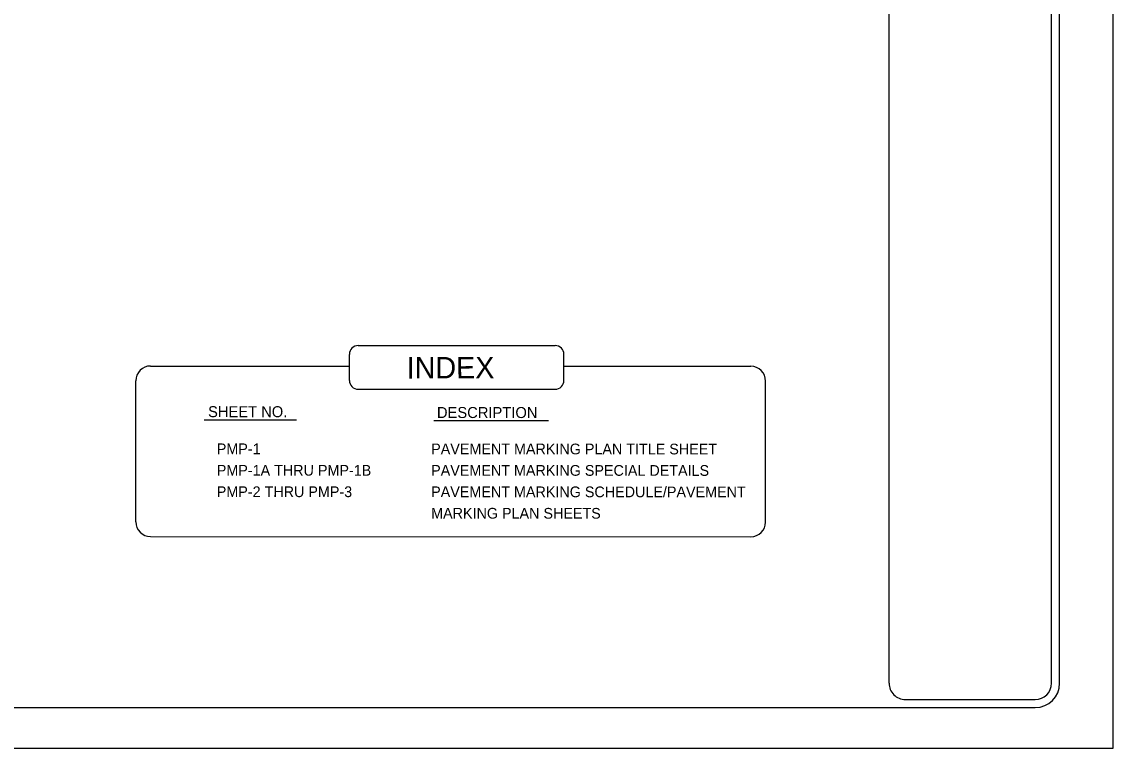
# Model space of a CAD drawing. Extents: x -63 to 3072, y 0 to 1100.
# Drawn here: x 1028 to 1700, y 0 to 447 of the extents above; entities that cross this region are included whole.
import ezdxf

# ---------------------------------------------------------------- set-up
doc = ezdxf.new("R2010")
doc.units = 0
for name, color, linetype in [('Draft_Plan_Labels', 7, 'Continuous'), ('Scratch_Level_0', 7, 'Continuous'), ('Sheet Data Text CELL', 7, 'Continuous'), ('Sheet_RDY_PE_Seal_Cell', 7, 'Continuous')]:
    doc.layers.add(name, color=color, linetype=linetype)

msp = doc.modelspace()

# ---------------------------------------------------------------- linework, layer by layer
at = {"layer": 'Scratch_Level_0'}
for p, q in [((1699.98, 0), (1699.98, 1100)), ((0, 0), (1699.98, 0))]:
    msp.add_line(p, q, dxfattribs=at)
at = {"layer": 'Sheet_RDY_PE_Seal_Cell'}
for p, q in [((1561.97, 39.96), (1562, 1059.93)), ((1662, 39.96), (1662, 1059.91)), ((1667, 39.99), (1667, 1059.91)), ((1229.66, 226.43), (1229.66, 242.45)), ((1361.82, 226.43), (1361.82, 242.45)), ((1107.27, 235.27), (1229.66, 235.22)), ((1361.82, 235.16), (1476.88, 235.1)), ((1098.14, 139.4), (1098.18, 226.19)), ((1485.93, 139.22), (1485.97, 226.01)), ((1140.18, 202.22), (1197.04, 202.19)), ((1281.57, 201.7), (1352.21, 201.67)), ((1107.22, 130.31), (1476.83, 130.14)), ((1571.99, 29.94), (1651.98, 29.94)), ((38.07, 24.99), (1652, 24.99))]:
    msp.add_line(p, q, dxfattribs=at)
for points in [[(1235.11, 247.9), (1356.36, 247.9)], [(1235.11, 220.97), (1356.36, 220.97)]]:
    msp.add_lwpolyline(points, dxfattribs=at)
for centre, radius, start, end in [((1235.11, 242.45), 5.45, 90, 180), ((1356.36, 242.45), 5.45, 360, 90), ((1107.26, 226.19), 9.09, 89.97341, 179.97341), ((1476.88, 226.02), 9.09, 359.97341, 89.97341), ((1235.11, 226.43), 5.45, 180, 270), ((1356.36, 226.43), 5.45, 270, 360), ((1107.22, 139.4), 9.09, 179.97341, 269.97341), ((1476.84, 139.23), 9.09, 269.97341, 359.97341), ((1571.99, 39.96), 10.02, 179.99864, 270), ((1651.98, 39.96), 10.02, 270, 360), ((1652, 39.99), 15, 270.00782, 0.00782)]:
    msp.add_arc(centre, radius, start, end, dxfattribs=at)

# ---------------------------------------------------------------- texts
at = {"layer": 'Draft_Plan_Labels'}
for s, height, p in [('SHEET NO.', 6.771, (1142.65, 203.79)), ('DESCRIPTION', 6.7709, (1283.59, 203.27)), ('PMP-1          ', 6.6, (1148.03, 181)), ('PAVEMENT MARKING PLAN TITLE SHEET', 6.6, (1280.03, 180.94)), ('PMP-1A THRU PMP-1B', 6.6, (1148.02, 167.8)), ('PAVEMENT MARKING SPECIAL DETAILS', 6.6, (1280.02, 167.74)), ('PMP-2 THRU PMP-3', 6.6, (1148.02, 154.6)), ('PAVEMENT MARKING SCHEDULE/PAVEMENT', 6.6, (1280.02, 154.54)), ('MARKING PLAN SHEETS', 6.6, (1280.01, 141.34))]:
    msp.add_text(s, height=height, rotation=359.97341, dxfattribs=at).set_placement(p)
at = {"layer": 'Sheet Data Text CELL'}
msp.add_text('INDEX', height=13.2, rotation=0.15565, dxfattribs=at).set_placement((1265.02, 227.58))

doc.saveas('drawing.dxf')
